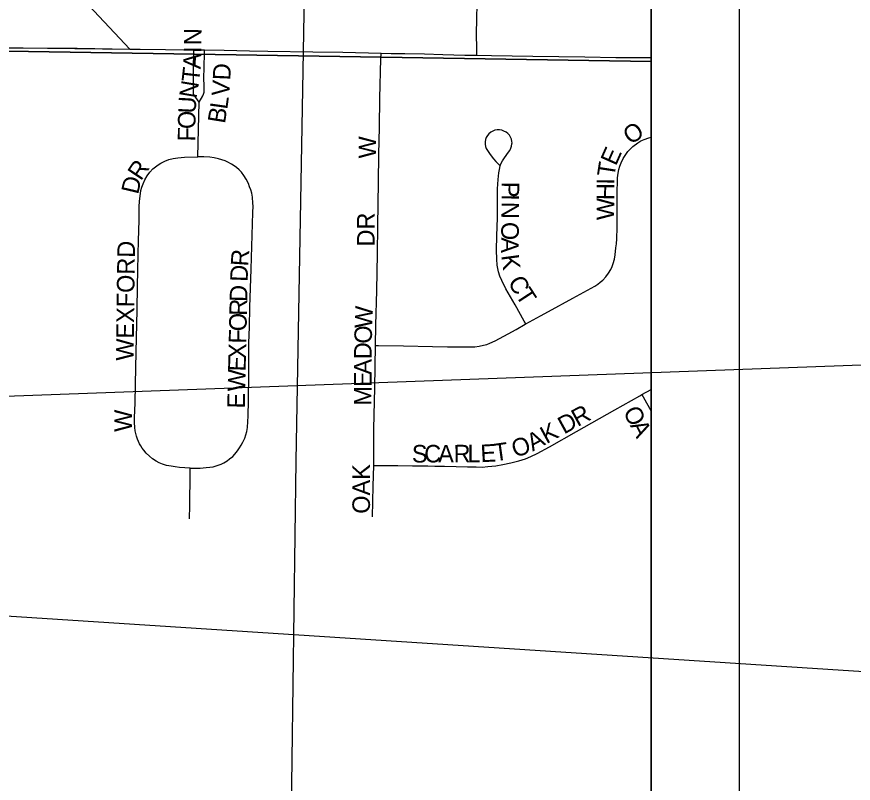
# Model space of a CAD drawing. Extents: x -5.6 to 34, y 0 to 22.
# Drawn here: x 8.177 to 9.13, y 18.084 to 18.957 of the extents above; entities that cross this region are included whole.
import ezdxf

# ---------------------------------------------------------------- set-up
doc = ezdxf.new("R2010")
doc.units = 0
for name, color, linetype in [('GM_X_Corporation', 7, 'Continuous'), ('GM_X_Minor_River', 7, 'Continuous'), ('GM_X_Section', 7, 'Continuous'), ('GM_X_Township', 7, 'Continuous'), ('GM_X_Township_Road', 7, 'Continuous'), ('GM_X_Township_Subdivision', 7, 'Continuous'), ('GM_X_Township_Subdivision_Text', 7, 'Continuous'), ('SH_Data', 7, 'Continuous'), ('SH_Text', 7, 'Continuous')]:
    doc.layers.add(name, color=color, linetype=linetype)

msp = doc.modelspace()

# ---------------------------------------------------------------- linework, layer by layer
at = {"layer": 'GM_X_Corporation'}
msp.add_lwpolyline([(6.45784, 18.92567), (6.46907, 18.9327), (6.47607, 18.93645), (6.48407, 18.94005), (6.49572, 18.94416), (6.51255, 18.9483), (6.52119, 18.94941), (6.52984, 18.95021), (6.54501, 18.95074), (6.59918, 18.94965), (6.62559, 18.94975), (6.98538, 18.94169), (7.00155, 18.94146), (7.62218, 18.92868), (7.63549, 18.92855), (7.82514, 18.92584), (7.83634, 18.92574), (8.30616, 18.92024), (7.90804, 19.34394), (7.82828, 19.42651), (8.24628, 19.4221), (8.54585, 19.9586)], dxfattribs=at)
at = {"layer": 'GM_X_Minor_River'}
msp.add_lwpolyline([(8.55502, 20.9), (8.54654, 20.63728), (8.52469, 19.87442), (8.51233, 19.41446), (8.50292, 18.87433), (8.49501, 18.45122), (8.48837, 17.94072), (8.48596, 17.51112), (8.48723, 17.30191), (8.48236, 16.7441), (8.47934, 16.08368), (8.47658, 15.74948)], dxfattribs=at)
at = {"layer": 'GM_X_Section'}
for points in [[(8.9, 18.90601), (8.9, 20.9), (7.5006, 20.9), (7.45777, 18.92939)], [(8.9, 16.76584), (8.9, 18.90601), (7.45777, 18.92939), (7.41826, 16.78712)]]:
    msp.add_lwpolyline(points, close=True, dxfattribs=at)
at = {"layer": 'GM_X_Township'}
msp.add_lwpolyline([(3.06358, 14.1), (8.9, 14.1), (8.9, 20.9), (2.1, 20.9), (2.1, 16.91076), (2.72419, 16.87066), (3.13885, 16.86164), (3.07452, 14.71213)], close=True, dxfattribs=at)
at = {"layer": 'GM_X_Township_Road'}
for points in [[(8.14406, 18.9221), (8.16877, 18.92176), (8.18453, 18.92163), (8.24626, 18.92119), (8.30616, 18.92024)], [(8.30616, 18.92024), (8.31776, 18.92006), (8.34664, 18.91989), (8.37286, 18.91948), (8.37885, 18.91941)], [(8.37885, 18.91941), (8.39133, 18.91924)], [(8.39133, 18.91924), (8.41353, 18.91897), (8.44239, 18.91831), (8.46339, 18.91797), (8.51455, 18.91717), (8.54866, 18.91664), (8.59231, 18.91552)], [(8.59231, 18.91552), (8.60375, 18.91521), (8.6195, 18.91514), (8.6418, 18.91493), (8.66276, 18.91414), (8.68769, 18.91343), (8.70136, 18.91325)], [(8.70136, 18.91325), (8.71789, 18.91302), (8.76512, 18.91217), (8.82416, 18.91124), (8.85959, 18.91061), (8.88063, 18.91053), (8.9, 18.9105)]]:
    msp.add_lwpolyline(points, dxfattribs=at)
at = {"layer": 'GM_X_Township_Subdivision'}
msp.add_line((8.8894, 18.52653), (8.9, 18.53254), dxfattribs=at)
for points in [[(8.70136, 18.91325), (8.70123, 18.92052), (8.70094, 18.93758), (8.70201, 18.98877), (8.70249, 19.01899), (8.70277, 19.03306)], [(8.38504, 18.85966), (8.3794, 18.86765), (8.3787, 18.86916), (8.37843, 18.87164), (8.37845, 18.8744), (8.37853, 18.88474), (8.37864, 18.89818), (8.37882, 18.9167), (8.37885, 18.91941)], [(8.38504, 18.85966), (8.38932, 18.86697), (8.39014, 18.8689), (8.39058, 18.87124), (8.39083, 18.87359), (8.3907, 18.87936), (8.39054, 18.88584), (8.39122, 18.91478), (8.39133, 18.91924)], [(8.58585, 18.58245), (8.58636, 18.60556), (8.58739, 18.64533), (8.58806, 18.68704), (8.58857, 18.71899), (8.58924, 18.76869), (8.58975, 18.80014), (8.5906, 18.83141), (8.59095, 18.86441), (8.59214, 18.90906), (8.59231, 18.91552)], [(8.38347, 18.79763), (8.38504, 18.85966)], [(8.75699, 18.60722), (8.75517, 18.61044), (8.74479, 18.62876), (8.73429, 18.64726), (8.72963, 18.65668), (8.7276, 18.66154), (8.72597, 18.66654), (8.72508, 18.67036), (8.72445, 18.67424), (8.72392, 18.68079), (8.72375, 18.69132), (8.72425, 18.70752), (8.72488, 18.72811), (8.72493, 18.75046), (8.72503, 18.761), (8.72556, 18.7715), (8.72636, 18.77935), (8.72696, 18.78323), (8.72793, 18.78705), (8.72883, 18.78952), (8.73062, 18.79302), (8.7328, 18.7963), (8.73755, 18.80262), (8.73894, 18.80483), (8.74007, 18.80721), (8.74088, 18.80972), (8.74136, 18.8123), (8.74143, 18.8136), (8.74135, 18.81491), (8.74083, 18.8175), (8.73984, 18.81993), (8.73843, 18.82213), (8.73664, 18.82406), (8.73454, 18.82565), (8.73222, 18.82688), (8.72972, 18.82772), (8.72713, 18.82815), (8.7245, 18.82815), (8.72192, 18.82773), (8.71944, 18.82684), (8.71715, 18.82554), (8.71513, 18.82386), (8.71344, 18.82185), (8.71213, 18.81957), (8.71123, 18.8171), (8.71076, 18.81452), (8.71075, 18.81188), (8.71119, 18.8093), (8.71207, 18.80682), (8.71335, 18.80451), (8.71591, 18.80112), (8.7177, 18.79876), (8.72041, 18.79527), (8.72287, 18.79234), (8.72717, 18.78785)], [(8.75699, 18.60722), (8.7737, 18.61619), (8.78291, 18.6213), (8.81052, 18.63637), (8.83573, 18.65027), (8.83895, 18.6523), (8.84194, 18.65456), (8.8447, 18.65709), (8.84806, 18.66086), (8.85113, 18.66493), (8.85378, 18.6692), (8.85542, 18.67258), (8.85671, 18.67609), (8.85802, 18.68096), (8.85888, 18.68598), (8.8597, 18.69373), (8.8602, 18.69843), (8.86081, 18.70415), (8.86122, 18.71713), (8.86127, 18.72624), (8.86098, 18.73936), (8.86117, 18.75386), (8.86169, 18.77359), (8.86219, 18.77898), (8.86295, 18.78304), (8.86413, 18.78701), (8.8657, 18.79082), (8.86811, 18.79562), (8.87092, 18.80029), (8.87341, 18.80359), (8.87626, 18.80661), (8.87895, 18.80924), (8.88468, 18.81335), (8.88819, 18.81557), (8.89195, 18.81735), (8.89714, 18.8191), (8.9, 18.81981)], [(8.37493, 18.44271), (8.36278, 18.44365), (8.3576, 18.44434), (8.35323, 18.44491), (8.34791, 18.44596), (8.34332, 18.44729), (8.33945, 18.44872), (8.33602, 18.45075), (8.33206, 18.45335), (8.32841, 18.45626), (8.32476, 18.45981), (8.32194, 18.46314), (8.32007, 18.46575), (8.31862, 18.46827), (8.31726, 18.47065), (8.3161, 18.47308), (8.315, 18.47599), (8.31381, 18.47909), (8.31277, 18.4823), (8.312, 18.48529), (8.31169, 18.48905), (8.31139, 18.49493), (8.31154, 18.50035), (8.31213, 18.51691), (8.31263, 18.53846), (8.31347, 18.57519), (8.31427, 18.62277), (8.3148, 18.65036), (8.31524, 18.66766), (8.31572, 18.68662), (8.3161, 18.70159), (8.31637, 18.71344), (8.31661, 18.72548), (8.31656, 18.73481), (8.31685, 18.74038), (8.31715, 18.74701), (8.31776, 18.75273), (8.31881, 18.75906), (8.31986, 18.76297), (8.32121, 18.76674), (8.32332, 18.77141), (8.32602, 18.77592), (8.32887, 18.78002), (8.33235, 18.78369), (8.33518, 18.78617), (8.33822, 18.7884), (8.34144, 18.79038), (8.34597, 18.79263), (8.3507, 18.79444), (8.35538, 18.79552), (8.36066, 18.79642), (8.36848, 18.79703), (8.38347, 18.79763)], [(8.37493, 18.44271), (8.38621, 18.44296), (8.39318, 18.4434), (8.39735, 18.44393), (8.401, 18.44445), (8.40568, 18.44584), (8.41003, 18.44741), (8.41298, 18.4488), (8.41697, 18.45124), (8.41975, 18.45333), (8.42323, 18.45609), (8.42583, 18.45888), (8.42878, 18.46271), (8.43104, 18.466), (8.43295, 18.46895), (8.43486, 18.47226), (8.43694, 18.47695), (8.43832, 18.48078), (8.4392, 18.48443), (8.44007, 18.48894), (8.44058, 18.49607), (8.44092, 18.50197), (8.44114, 18.52003), (8.4416, 18.54835), (8.4416, 18.55704), (8.44171, 18.58573), (8.44224, 18.60343), (8.44294, 18.62634), (8.44425, 18.66934), (8.44612, 18.73403), (8.4464, 18.74134), (8.44626, 18.74472), (8.44568, 18.75145), (8.44499, 18.75596), (8.44386, 18.75991), (8.44255, 18.76343), (8.44116, 18.76725), (8.43873, 18.77212), (8.43612, 18.77611), (8.43333, 18.77994), (8.43062, 18.78285), (8.4276, 18.78532), (8.42499, 18.78721), (8.42186, 18.78914), (8.41769, 18.7914), (8.41457, 18.79279), (8.41092, 18.79416), (8.4071, 18.79521), (8.40234, 18.7962), (8.39719, 18.79695), (8.39037, 18.79733), (8.38347, 18.79763)], [(8.58585, 18.58245), (8.58928, 18.58258), (8.61793, 18.58231), (8.65071, 18.58132), (8.66772, 18.58119), (8.68205, 18.58088), (8.69394, 18.58096), (8.69904, 18.58116), (8.70409, 18.58175), (8.70904, 18.58276), (8.71265, 18.58382), (8.71621, 18.58516), (8.72202, 18.5879), (8.7371, 18.5957), (8.74613, 18.60094), (8.75635, 18.60688), (8.75699, 18.60722)], [(8.58382, 18.4459), (8.58398, 18.48776), (8.585, 18.53432), (8.58585, 18.58245)], [(8.58382, 18.4459), (8.61129, 18.44575), (8.62806, 18.44552), (8.64546, 18.44525), (8.65361, 18.44511), (8.66438, 18.44491), (8.67776, 18.44468), (8.69079, 18.44444), (8.7006, 18.4442), (8.70724, 18.4441), (8.71387, 18.44456), (8.72311, 18.44556), (8.73098, 18.4468), (8.74009, 18.44872), (8.74908, 18.45113), (8.75668, 18.4536), (8.7629, 18.45604), (8.77012, 18.45949), (8.78409, 18.46697), (8.81493, 18.48456), (8.85839, 18.50911), (8.88702, 18.52518), (8.8894, 18.52653)], [(8.8894, 18.52653), (8.89076, 18.52411), (8.9, 18.50783)], [(8.58264, 18.38718), (8.58314, 18.42209), (8.58382, 18.4459)], [(8.37391, 18.3852), (8.37425, 18.40031), (8.37453, 18.41317), (8.37475, 18.42325), (8.37493, 18.44271)]]:
    msp.add_lwpolyline(points, dxfattribs=at)
at = {"layer": 'SH_Data'}
for p, q in [((9, 21), (9, 14)), ((8.9, 20.9), (8.9, 14.1))]:
    msp.add_line(p, q, dxfattribs=at)
at = {"layer": 'SH_Text'}
msp.add_lwpolyline([(10.62193, 18.11475), (5.69645, 18.43444), (10.62193, 18.61475)], close=True, dxfattribs=at)

# ---------------------------------------------------------------- texts
at = {"layer": 'GM_X_Township_Subdivision_Text'}
for s, rotation, p in [('N', 89.75621, (8.38766, 18.92463)), ('A', 86.91904, (8.38658, 18.89717)), ('I', 89.33328, (8.38756, 18.91566)), ('D', 87.55624, (8.4205, 18.88438)), ('T', 83.59868, (8.3849, 18.88192)), ('V', 85.38297, (8.41904, 18.86602)), ('N', 80.58079, (8.38187, 18.86341)), ('L', 82.10178, (8.41697, 18.85086)), ('U', 86.96079, (8.381, 18.84642)), ('O', 89.41856, (8.38083, 18.82905)), ('B', 80.6814, (8.41432, 18.8347)), ('F', 89.42623, (8.38069, 18.81497)), ('O', 33.65976, (8.8763, 18.81066)), ('W', 90, (8.58662, 18.79567)), ('E', 66.0264, (8.85968, 18.78632)), ('R', 56.00681, (8.31872, 18.76936)), ('T', 81.19776, (8.85792, 18.77374)), ('D', 76.74821, (8.31544, 18.75397)), ('I', 89.62867, (8.85792, 18.76571)), ('P', 269.45355, (8.72966, 18.76915)), ('H', 89.62837, (8.85781, 18.74811)), ('I', 269.45268, (8.72953, 18.75507)), ('N', 269.4535, (8.72945, 18.74626)), ('W', 89.63013, (8.85766, 18.72523)), ('DR', 90, (8.58486, 18.69534)), ('O', 269.46359, (8.72923, 18.72338)), ('A', 269.4535, (8.72906, 18.70578)), ('WEXFORD', 89.27389, (8.3103, 18.56504)), ('R', 85.96456, (8.44088, 18.67227)), ('K', 277.64515, (8.72909, 18.68507)), ('D', 87.92339, (8.44025, 18.65486)), ('C', 298.67906, (8.7362, 18.65528)), ('D', 88.71045, (8.43974, 18.63205)), ('T', 303.10957, (8.74467, 18.63993)), ('R', 88.73467, (8.43939, 18.61622)), ('W', 87.71274, (8.5821, 18.60185)), ('O', 88.71045, (8.43899, 18.59862)), ('F', 88.72654, (8.43868, 18.58454)), ('O', 88.03258, (8.5815, 18.58429)), ('X', 88.72035, (8.43828, 18.56694)), ('D', 89.54093, (8.58136, 18.56683)), ('E', 88.71603, (8.43796, 18.55286)), ('A', 89.98125, (8.58135, 18.54927)), ('W', 88.72383, (8.43745, 18.52999)), ('E', 89.97267, (8.58135, 18.53519)), ('M', 89.98178, (8.58134, 18.51407)), ('E', 88.71603, (8.43702, 18.51063)), ('R', 28.78523, (8.81608, 18.48949)), ('O', 296.60415, (8.86745, 18.5074)), ('W', 90, (8.30854, 18.48415)), ('D', 28.76736, (8.80065, 18.48102)), ('K', 28.78277, (8.78059, 18.47001)), ('A', 297.23004, (8.87544, 18.49145)), ('A', 28.1726, (8.76487, 18.46158)), ('O', 18.40574, (8.74476, 18.45455)), ('S', 0.19126, (8.62736, 18.44919)), ('C', 0.1943, (8.64144, 18.44924)), ('A', 0.19674, (8.65727, 18.44929)), ('R', 0.17002, (8.67487, 18.44935)), ('L', 0.19721, (8.69072, 18.4494)), ('E', 3.20468, (8.70595, 18.44948)), ('T', 8.06333, (8.72185, 18.45045)), ('OAK', 90, (8.57958, 18.39086))]:
    msp.add_text(s, height=0.02, rotation=rotation, dxfattribs=at).set_placement(p)

doc.saveas('drawing.dxf')
